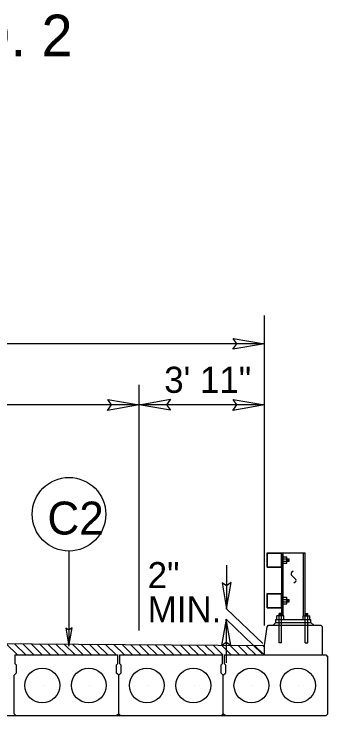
# Model space of a CAD drawing. Extents: x 575722 to 576066, y -53107 to -52774.
# Drawn here: x 575912.29 to 575921.31, y -52878.83 to -52858.63 of the extents above; entities that cross this region are included whole.
import ezdxf

# ---------------------------------------------------------------- set-up
doc = ezdxf.new("R2010")
doc.units = 0
for name, color, linetype in [('Default', 7, 'Continuous'), ('Old_Level_11', 7, 'Continuous'), ('Prop Dimension', 7, 'Continuous'), ('Prop Dimension Text', 7, 'Continuous'), ('Typical ID Circle CELL', 7, 'Continuous'), ('Typical Terminator CELL', 7, 'Continuous'), ('Typical Text ID Circle CELL', 7, 'Continuous')]:
    doc.layers.add(name, color=color, linetype=linetype)

msp = doc.modelspace()

# ---------------------------------------------------------------- linework, layer by layer
at = {"layer": 'Default'}
for p, q in [((575919.566, -52874.552), (575919.566, -52874.134)), ((575919.566, -52874.134), (575919.984, -52874.134)), ((575919.577, -52874.145), (575919.973, -52874.145)), ((575919.577, -52874.541), (575919.577, -52874.145)), ((575919.973, -52874.541), (575919.973, -52874.145)), ((575919.984, -52875.949), (575919.984, -52874.134)), ((575919.984, -52874.134), (575920.651, -52874.134)), ((575919.984, -52874.552), (575919.984, -52874.134)), ((575920.025, -52875.949), (575920.025, -52874.134)), ((575920.025, -52874.249), (575920.131, -52874.249)), ((575920.025, -52874.312), (575920.192, -52874.312)), ((575920.131, -52874.437), (575920.131, -52874.249)), ((575920.137, -52874.374), (575920.135, -52874.312)), ((575920.148, -52874.374), (575920.145, -52874.312)), ((575920.158, -52874.374), (575920.155, -52874.312)), ((575920.168, -52874.374), (575920.165, -52874.312)), ((575920.178, -52874.374), (575920.176, -52874.312)), ((575920.192, -52874.374), (575920.192, -52874.312)), ((575920.61, -52875.949), (575920.61, -52874.134)), ((575920.651, -52875.949), (575920.651, -52874.134)), ((575920.025, -52874.374), (575920.192, -52874.374)), ((575920.025, -52874.437), (575920.131, -52874.437)), ((575919.566, -52874.552), (575919.984, -52874.552)), ((575919.577, -52874.541), (575919.973, -52874.541)), ((575920.309, -52874.66), (575920.283, -52874.678)), ((575920.279, -52874.795), (575920.37, -52874.882)), ((575920.364, -52874.985), (575920.332, -52875.011)), ((575919.566, -52875.72), (575919.566, -52875.303)), ((575919.566, -52875.303), (575919.984, -52875.303)), ((575919.577, -52875.313), (575919.973, -52875.313)), ((575919.577, -52875.71), (575919.577, -52875.313)), ((575919.973, -52875.71), (575919.973, -52875.313)), ((575919.984, -52875.72), (575919.984, -52875.303)), ((575920.025, -52875.417), (575920.131, -52875.417)), ((575920.025, -52875.48), (575920.192, -52875.48)), ((575920.131, -52875.606), (575920.131, -52875.417)), ((575920.137, -52875.543), (575920.135, -52875.48)), ((575920.148, -52875.543), (575920.145, -52875.48)), ((575920.158, -52875.543), (575920.155, -52875.48)), ((575920.168, -52875.543), (575920.165, -52875.48)), ((575920.178, -52875.543), (575920.176, -52875.48)), ((575920.192, -52875.543), (575920.192, -52875.48)), ((575919.566, -52875.72), (575919.984, -52875.72)), ((575919.577, -52875.71), (575919.973, -52875.71)), ((575920.025, -52875.543), (575920.192, -52875.543)), ((575920.025, -52875.606), (575920.131, -52875.606)), ((575919.905, -52876.054), (575919.905, -52875.887)), ((575919.978, -52875.887), (575919.905, -52875.887)), ((575919.978, -52875.901), (575919.905, -52875.904)), ((575919.978, -52875.911), (575919.905, -52875.914)), ((575919.978, -52875.922), (575919.905, -52875.924)), ((575919.978, -52876.054), (575919.978, -52875.887)), ((575920.656, -52876.054), (575920.656, -52875.887)), ((575920.656, -52875.887), (575920.73, -52875.887)), ((575920.656, -52875.901), (575920.73, -52875.904)), ((575920.656, -52875.911), (575920.73, -52875.914)), ((575920.656, -52875.922), (575920.73, -52875.924)), ((575920.73, -52876.054), (575920.73, -52875.887)), ((575919.817, -52876.054), (575920.818, -52876.054)), ((575919.817, -52876.137), (575919.817, -52876.054)), ((575920.041, -52875.949), (575919.843, -52875.949)), ((575919.843, -52876.054), (575919.843, -52875.949)), ((575919.978, -52875.932), (575919.905, -52875.935)), ((575919.978, -52875.942), (575919.905, -52875.945)), ((575919.905, -52876.722), (575919.905, -52876.054)), ((575919.978, -52876.722), (575919.978, -52876.054)), ((575920.041, -52876.054), (575920.041, -52875.949)), ((575920.594, -52875.949), (575920.792, -52875.949)), ((575920.594, -52876.054), (575920.594, -52875.949)), ((575920.656, -52875.932), (575920.73, -52875.935)), ((575920.656, -52875.942), (575920.73, -52875.945)), ((575920.656, -52876.722), (575920.656, -52876.054)), ((575920.73, -52876.722), (575920.73, -52876.054)), ((575920.792, -52876.054), (575920.792, -52875.949)), ((575920.818, -52876.137), (575920.818, -52876.054)), ((575919.483, -52876.805), (575919.56, -52876.263)), ((575919.56, -52876.263), (575919.602, -52876.221)), ((575919.602, -52876.221), (575921.11, -52876.221)), ((575919.733, -52876.221), (575919.817, -52876.137)), ((575919.817, -52876.137), (575920.818, -52876.137)), ((575920.902, -52876.221), (575920.818, -52876.137)), ((575921.152, -52876.263), (575921.11, -52876.221)), ((575921.152, -52877.076), (575921.152, -52876.263)), ((575919.978, -52876.722), (575919.905, -52876.722)), ((575920.656, -52876.722), (575920.73, -52876.722)), ((575912.391, -52877.076), (575912.067, -52876.752)), ((575912.627, -52877.076), (575912.304, -52876.754)), ((575912.863, -52877.076), (575912.542, -52876.755)), ((575913.1, -52877.076), (575912.78, -52876.757)), ((575913.336, -52877.076), (575913.018, -52876.759)), ((575913.572, -52877.076), (575913.256, -52876.76)), ((575913.808, -52877.076), (575913.494, -52876.762)), ((575914.044, -52877.076), (575913.731, -52876.764)), ((575914.28, -52877.076), (575913.969, -52876.766)), ((575914.516, -52877.076), (575914.207, -52876.767)), ((575914.752, -52877.076), (575914.445, -52876.769)), ((575914.989, -52877.076), (575914.683, -52876.771)), ((575915.225, -52877.076), (575914.921, -52876.772)), ((575915.461, -52877.076), (575915.158, -52876.774)), ((575915.697, -52877.076), (575915.396, -52876.776)), ((575915.933, -52877.076), (575915.634, -52876.778)), ((575916.169, -52877.076), (575915.872, -52876.779)), ((575916.405, -52877.076), (575916.11, -52876.781)), ((575916.641, -52877.076), (575916.348, -52876.783)), ((575916.878, -52877.076), (575916.585, -52876.784)), ((575917.114, -52877.076), (575916.823, -52876.786)), ((575917.35, -52877.076), (575917.061, -52876.788)), ((575917.586, -52877.076), (575917.299, -52876.789)), ((575917.822, -52877.076), (575917.537, -52876.791)), ((575918.058, -52877.076), (575917.775, -52876.793)), ((575918.294, -52877.076), (575918.012, -52876.795)), ((575918.53, -52877.076), (575918.25, -52876.796)), ((575918.766, -52877.076), (575918.488, -52876.798)), ((575919.003, -52877.076), (575918.726, -52876.8)), ((575919.239, -52877.076), (575918.964, -52876.801)), ((575919.475, -52877.076), (575919.202, -52876.803)), ((575919.483, -52876.848), (575919.44, -52876.805)), ((575919.483, -52877.076), (575919.483, -52876.805)), ((575912.291, -52877.076), (575912.291, -52877.076)), ((575912.322, -52877.327), (575912.322, -52877.076)), ((575912.322, -52877.076), (575915.265, -52877.076)), ((575915.265, -52877.076), (575915.265, -52877.327)), ((575915.297, -52877.076), (575915.297, -52877.076)), ((575915.298, -52877.076), (575915.298, -52877.076)), ((575915.328, -52877.327), (575915.328, -52877.076)), ((575915.328, -52877.076), (575918.272, -52877.076)), ((575918.272, -52877.076), (575918.272, -52877.327)), ((575918.335, -52877.076), (575921.247, -52877.076)), ((575918.335, -52877.327), (575918.335, -52877.076)), ((575919.483, -52877.076), (575921.152, -52877.076)), ((575921.247, -52877.076), (575921.31, -52877.139)), ((575921.31, -52878.768), (575921.31, -52877.139)), ((575912.322, -52877.327), (575912.353, -52877.358)), ((575915.265, -52877.327), (575915.234, -52877.358)), ((575915.328, -52877.327), (575915.359, -52877.358)), ((575918.272, -52877.327), (575918.241, -52877.358)), ((575918.335, -52877.327), (575918.366, -52877.358)), ((575912.353, -52877.358), (575912.353, -52877.598)), ((575915.234, -52877.598), (575915.234, -52877.358)), ((575915.359, -52877.358), (575915.359, -52877.598)), ((575918.241, -52877.598), (575918.241, -52877.358)), ((575918.366, -52877.358), (575918.366, -52877.598)), ((575912.29, -52877.661), (575912.353, -52877.598)), ((575912.291, -52878.768), (575912.291, -52877.661)), ((575915.297, -52877.661), (575915.234, -52877.598)), ((575915.297, -52877.661), (575915.359, -52877.598)), ((575915.297, -52878.768), (575915.297, -52877.661)), ((575915.298, -52878.768), (575915.298, -52877.661)), ((575918.303, -52877.661), (575918.241, -52877.598)), ((575918.303, -52877.661), (575918.366, -52877.598)), ((575918.303, -52878.768), (575918.303, -52877.661)), ((575918.303, -52878.768), (575918.303, -52877.661)), ((575913.125, -52877.953), (575913.125, -52877.953)), ((575914.461, -52877.953), (575914.461, -52877.953)), ((575916.132, -52877.953), (575916.132, -52877.953)), ((575917.468, -52877.953), (575917.468, -52877.953)), ((575919.139, -52877.953), (575919.139, -52877.953)), ((575920.475, -52877.953), (575920.475, -52877.953)), ((575921.254, -52878.83), (575888.313, -52878.83)), ((575912.353, -52878.83), (575912.29, -52878.768)), ((575915.234, -52878.83), (575912.353, -52878.83)), ((575915.297, -52878.768), (575915.234, -52878.83)), ((575915.359, -52878.83), (575915.297, -52878.768)), ((575918.241, -52878.83), (575915.359, -52878.83)), ((575918.303, -52878.768), (575918.241, -52878.83)), ((575918.366, -52878.83), (575918.303, -52878.768)), ((575921.247, -52878.83), (575918.366, -52878.83)), ((575921.31, -52878.768), (575921.247, -52878.83))]:
    msp.add_line(p, q, dxfattribs=at)
msp.add_lwpolyline([(575890.01, -52876.805), (575904.783, -52876.699), (575919.483, -52876.805)], dxfattribs=at)
for centre in [(575913.101, -52877.953), (575914.437, -52877.953), (575916.106, -52877.953), (575917.442, -52877.953), (575919.111, -52877.953), (575920.448, -52877.953)]:
    msp.add_circle(centre, 0.501, dxfattribs=at)
for centre, radius, start, end in [((575920.322, -52874.738), 0.071, 122.9142, 232.7131), ((575920.331, -52874.931), 0.0631, 301.9827, 50.2683)]:
    msp.add_arc(centre, radius, start, end, dxfattribs=at)
at = {"layer": 'Old_Level_11'}
for p, q in [((575919.483, -52876.227), (575919.483, -52867.304)), ((575919.483, -52868.121), (575890.01, -52868.121)), ((575915.883, -52876.376), (575915.883, -52869.304)), ((575915.883, -52869.878), (575899.683, -52869.878)), ((575919.483, -52869.878), (575915.883, -52869.878)), ((575919.437, -52876.742), (575918.399, -52875.746)), ((575919.422, -52877.045), (575918.385, -52876.049))]:
    msp.add_line(p, q, dxfattribs=at)
for points in [[(575918.583, -52867.966), (575919.483, -52868.121), (575918.578, -52868.281), (575918.693, -52868.121)], [(575914.983, -52869.723), (575915.883, -52869.878), (575914.978, -52870.038), (575915.093, -52869.878)], [(575916.783, -52870.033), (575915.883, -52869.878), (575916.788, -52869.718), (575916.673, -52869.878)], [(575918.583, -52869.723), (575919.483, -52869.878), (575918.578, -52870.038), (575918.693, -52869.878)]]:
    msp.add_lwpolyline(points, close=True, dxfattribs=at)
at = {"layer": 'Prop Dimension'}
for p, q in [((575918.399, -52874.496), (575918.399, -52875.746)), ((575918.385, -52876.049), (575918.385, -52877.299))]:
    msp.add_line(p, q, dxfattribs=at)
at = {"layer": 'Typical ID Circle CELL'}
msp.add_line((575913.868, -52874.084), (575913.868, -52876.818), dxfattribs=at)
msp.add_circle((575913.868, -52873.026), 1.058, dxfattribs=at)
at = {"layer": 'Typical Terminator CELL'}
for points in [[(575918.27, -52874.996), (575918.399, -52875.746), (575918.532, -52874.992), (575918.399, -52875.088)], [(575918.515, -52876.798), (575918.385, -52876.049), (575918.252, -52876.803), (575918.385, -52876.707)], [(575913.779, -52876.302), (575913.868, -52876.818), (575913.959, -52876.299), (575913.868, -52876.365)]]:
    msp.add_lwpolyline(points, close=True, dxfattribs=at)

# ---------------------------------------------------------------- texts
at = {"layer": 'Old_Level_11'}
for s, p in [('3\' 11"', (575916.605, -52869.533)), ('2"', (575916.13, -52875.153)), ('MIN.', (575916.13, -52876.136))]:
    msp.add_text(s, height=0.75, rotation=360, dxfattribs=at).set_placement(p)
at = {"layer": 'Prop Dimension Text'}
msp.add_text('TYPICAL SECTION NO. 2', height=1.2, dxfattribs=at).set_placement((575895.068, -52859.851))
at = {"layer": 'Typical Text ID Circle CELL'}
msp.add_text('C2', height=0.9469, dxfattribs=at).set_placement((575913.25, -52873.61))

doc.saveas('drawing.dxf')
